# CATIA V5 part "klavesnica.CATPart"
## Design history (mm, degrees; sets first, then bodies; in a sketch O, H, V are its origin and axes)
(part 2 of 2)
  Draft30: PullDir end face of Pocket19, Angle 33, SupportToDraft (face of Pocket19 from Sketch48.A1; face of Pocket19 from Sketch48.A2; face of Pocket19 from Sketch48.A3; face of Pocket19 from Sketch48.A10; face of Pocket19 from Sketch48.A11; face of Pocket19 from Sketch48.A12; face of Pocket19 from Sketch48.A13; face of Pocket19 from Sketch48.A4; face of Pocket19 from Sketch48.L1; face of Pocket19 from Sketch48.A5; face of Pocket19 from Sketch48.L2; face of Pocket19 from Sketch48.A6; face of Pocket19 from Sketch48.L3; face of Pocket19 from Sketch48.A7; face of Pocket19 from Sketch48.L4; face of Pocket19 from Sketch48.A8; face of Pocket19 from Sketch48.L5; face of Pocket19 from Sketch48.A9; face of Pocket19 from Sketch48.L6), Neutral end face of Pocket19
  Fillet15: radius 0.5, on edge [end face of Pocket19 | face of Pocket19 from Sketch48.A1]; edge [end face of Pocket19 | face of Pocket19 from Sketch48.A2]; edge [end face of Pocket19 | face of Pocket19 from Sketch48.A3]; edge [end face of Pocket19 | face of Pocket19 from Sketch48.A10]; edge [end face of Pocket19 | face of Pocket19 from Sketch48.A11]; edge [end face of Pocket19 | face of Pocket19 from Sketch48.A12]; edge [end face of Pocket19 | face of Pocket19 from Sketch48.A13]; edge [end face of Pocket19 | face of Pocket19 from Sketch48.A4]; edge [end face of Pocket19 | face of Pocket19 from Sketch48.L1]; edge [end face of Pocket19 | face of Pocket19 from Sketch48.A5]; edge [end face of Pocket19 | face of Pocket19 from Sketch48.L2]; edge [end face of Pocket19 | face of Pocket19 from Sketch48.A6]; edge [end face of Pocket19 | face of Pocket19 from Sketch48.L3]; edge [end face of Pocket19 | face of Pocket19 from Sketch48.A7]; edge [end face of Pocket19 | face of Pocket19 from Sketch48.L4]; edge [end face of Pocket19 | face of Pocket19 from Sketch48.A8]; edge [end face of Pocket19 | face of Pocket19 from Sketch48.L5]; edge [end face of Pocket19 | face of Pocket19 from Sketch48.A9]; edge [end face of Pocket19 | face of Pocket19 from Sketch48.L6]
  Fillet16: radius 0.5, on edge [face of Pocket19 from Sketch48.A1 | start face of Pad1]; edge [face of Pocket19 from Sketch48.A2 | start face of Pad1]; edge [face of Pocket19 from Sketch48.A3 | start face of Pad1]; edge [face of Pocket19 from Sketch48.A10 | start face of Pad1]; edge [face of Pocket19 from Sketch48.A11 | start face of Pad1]; edge [face of Pocket19 from Sketch48.A12 | start face of Pad1]; edge [face of Pocket19 from Sketch48.A13 | start face of Pad1]; edge [face of Pocket19 from Sketch48.A4 | start face of Pad1]; edge [face of Pocket19 from Sketch48.L1 | start face of Pad1]; edge [face of Pocket19 from Sketch48.A5 | start face of Pad1]; edge [face of Pocket19 from Sketch48.L2 | start face of Pad1]; edge [face of Pocket19 from Sketch48.A6 | start face of Pad1]; edge [face of Pocket19 from Sketch48.L3 | start face of Pad1]; edge [face of Pocket19 from Sketch48.A7 | start face of Pad1]; edge [face of Pocket19 from Sketch48.L4 | start face of Pad1]; edge [face of Pocket19 from Sketch48.A8 | start face of Pad1]; edge [face of Pocket19 from Sketch48.L5 | start face of Pad1]; edge [face of Pocket19 from Sketch48.A9 | start face of Pad1]; edge [face of Pocket19 from Sketch48.L6 | start face of Pad1]
  Sketch49 on start face of Pad1, origin (0, 0, 0), H (1, 0, 0), V (0, -1, 0)
    line L1 (-17, -10.5) -> (-17, -7.5)
    line L2 (-10, -7.5) -> (-10, -10.5)
    arc A1 centre (-13.5, -7.5) radius 3.5 from (-17, -7.5) to (-10, -7.5) cw
    arc A2 centre (-13.5, -10.5) radius 3.5 from (-10, -10.5) to (-17, -10.5) cw
    line L3 (-6, -3.5) -> (-3, -3.5)
    line L4 (-3, 3.5) -> (-6, 3.5)
    arc A3 centre (-6, 0) radius 3.5 from (-6, 3.5) to (-6, -3.5) ccw
    arc A4 centre (-3, 0) radius 3.5 from (-3, -3.5) to (-3, 3.5) ccw
    line L5 (-10, 7.5) -> (-10, 10.5)
    line L6 (-17, 10.5) -> (-17, 7.5)
    arc A5 centre (-13.5, 10.5) radius 3.5 from (-10, 10.5) to (-17, 10.5) ccw
    arc A6 centre (-13.5, 7.5) radius 3.5 from (-17, 7.5) to (-10, 7.5) ccw
    arc A7 centre (-21, 0) radius 3.5 from (-21, 3.5) to (-21, -3.5) cw
    arc A8 centre (-24, 0) radius 3.5 from (-24, -3.5) to (-24, 3.5) cw
    line L7 (-24, 3.5) -> (-21, 3.5)
    line L8 (-21, -3.5) -> (-24, -3.5)
  Pocket20: profile Sketch49, direction (0, 0, 1), length 1, opposite side up to start face of Pad1
  Draft31: PullDir end face of Pocket20, Angle 33, SupportToDraft (face of Pocket20 from Sketch49.L1; face of Pocket20 from Sketch49.A1; face of Pocket20 from Sketch49.L2; face of Pocket20 from Sketch49.A2; face of Pocket20 from Sketch49.L3; face of Pocket20 from Sketch49.A4; face of Pocket20 from Sketch49.L4; face of Pocket20 from Sketch49.A3; face of Pocket20 from Sketch49.L5; face of Pocket20 from Sketch49.A5; face of Pocket20 from Sketch49.L6; face of Pocket20 from Sketch49.A6; face of Pocket20 from Sketch49.A7; face of Pocket20 from Sketch49.L8; face of Pocket20 from Sketch49.A8; face of Pocket20 from Sketch49.L7), Neutral end face of Pocket20
  Fillet17: radius 0.5, on edge [end face of Pocket20 | face of Pocket20 from Sketch49.L1]; edge [end face of Pocket20 | face of Pocket20 from Sketch49.A1]; edge [end face of Pocket20 | face of Pocket20 from Sketch49.L2]; edge [end face of Pocket20 | face of Pocket20 from Sketch49.A2]; edge [end face of Pocket20 | face of Pocket20 from Sketch49.L3]; edge [end face of Pocket20 | face of Pocket20 from Sketch49.A4]; edge [end face of Pocket20 | face of Pocket20 from Sketch49.L4]; edge [end face of Pocket20 | face of Pocket20 from Sketch49.A3]; edge [end face of Pocket20 | face of Pocket20 from Sketch49.L5]; edge [end face of Pocket20 | face of Pocket20 from Sketch49.A5]; edge [end face of Pocket20 | face of Pocket20 from Sketch49.L6]; edge [end face of Pocket20 | face of Pocket20 from Sketch49.A6]; edge [end face of Pocket20 | face of Pocket20 from Sketch49.A7]; edge [end face of Pocket20 | face of Pocket20 from Sketch49.L8]; edge [end face of Pocket20 | face of Pocket20 from Sketch49.A8]; edge [end face of Pocket20 | face of Pocket20 from Sketch49.L7]
  Fillet18: radius 0.5, on edge [face of Pocket20 from Sketch49.L1 | start face of Pad1]; edge [face of Pocket20 from Sketch49.A1 | start face of Pad1]; edge [face of Pocket20 from Sketch49.L2 | start face of Pad1]; edge [face of Pocket20 from Sketch49.A2 | start face of Pad1]; edge [face of Pocket20 from Sketch49.L3 | start face of Pad1]; edge [face of Pocket20 from Sketch49.A4 | start face of Pad1]; edge [face of Pocket20 from Sketch49.L4 | start face of Pad1]; edge [face of Pocket20 from Sketch49.A3 | start face of Pad1]; edge [face of Pocket20 from Sketch49.L5 | start face of Pad1]; edge [face of Pocket20 from Sketch49.A5 | start face of Pad1]; edge [face of Pocket20 from Sketch49.L6 | start face of Pad1]; edge [face of Pocket20 from Sketch49.A6 | start face of Pad1]; edge [face of Pocket20 from Sketch49.A7 | start face of Pad1]; edge [face of Pocket20 from Sketch49.L8 | start face of Pad1]; edge [face of Pocket20 from Sketch49.A8 | start face of Pad1]; edge [face of Pocket20 from Sketch49.L7 | start face of Pad1]
  Sketch50 on start face of Pad1, origin (0, 0, 0), H (1, 0, 0), V (0, -1, 0)
    circle A1 centre (20.4629, 14.0037) radius 3.5
  Pocket21: profile Sketch50, direction (0, 0, 1), length 1, opposite side up to start face of Pad1
  Draft32: PullDir end face of Pocket21, Angle 33, SupportToDraft face of Pocket21 from Sketch50.A1, Neutral end face of Pocket21
  Fillet19: radius 0.5, on edge [face of Pocket21 from Sketch50.A1 | end face of Pocket21]
  Fillet20: radius 0.5, on edge [face of Pocket21 from Sketch50.A1 | start face of Pad1]
  Sketch51 on start face of Pad1, origin (0, 0, 0), H (1, 0, 0), V (0, -1, 0)
    circle A1 centre (29.9629, 14.0037) radius 3.5
  Pocket22: profile Sketch51, direction (0, 0, 1), length 1, opposite side up to start face of Pad1
  Draft33: PullDir end face of Pocket22, Angle 33, SupportToDraft face of Pocket22 from Sketch51.A1, Neutral end face of Pocket22
  Fillet21: radius 0.5, on edge [face of Pocket22 from Sketch51.A1 | end face of Pocket22]
  Fillet22: radius 0.5, on edge [face of Pocket22 from Sketch51.A1 | start face of Pad1]
  Sketch52 on start face of Pad1, origin (0, 0, 0), H (1, 0, 0), V (0, -1, 0)
    circle A1 centre (12, 0) radius 3.5
  Pocket23: profile Sketch52, direction (0, 0, 1), length 1, opposite side up to start face of Pad1
  Draft34: PullDir end face of Pocket23, Angle 33, SupportToDraft face of Pocket23 from Sketch52.A1, Neutral end face of Pocket23
  Fillet23: radius 0.5, on edge [face of Pocket23 from Sketch52.A1 | end face of Pocket23]
  Fillet24: radius 0.5, on edge [face of Pocket23 from Sketch52.A1 | start face of Pad1]
  Sketch53 on start face of Pad1, origin (0, 0, 0), H (1, 0, 0), V (0, -1, 0)
    circle A1 centre (0.8728, -12.5) radius 4.5
    circle A2 centre (0.8728, 12.5) radius 4.5
  Pocket24: profile Sketch53, direction (0, 0, 1), length 1, opposite side up to start face of Pad1
  Draft35: PullDir end face of Pocket24, Angle 33, SupportToDraft (face of Pocket24 from Sketch53.A1; face of Pocket24 from Sketch53.A2), Neutral end face of Pocket24
  Fillet25: radius 0.5, on edge [end face of Pocket24 | face of Pocket24 from Sketch53.A1]; edge [end face of Pocket24 | face of Pocket24 from Sketch53.A2]
  Fillet26: radius 0.5, on edge [face of Pocket24 from Sketch53.A1 | start face of Pad1]; edge [face of Pocket24 from Sketch53.A2 | start face of Pad1]
  Sketch54 on start face of Pad1, origin (0, 0, 0), H (1, 0, 0), V (0, -1, 0)
    circle A1 centre (-27.8728, 12.5) radius 4.5
    circle A2 centre (-27.8728, -12.5) radius 4.5
  Pocket25: profile Sketch54, direction (0, 0, 1), length 1, opposite side up to start face of Pad1
  Draft36: PullDir end face of Pocket25, Angle 33, SupportToDraft (face of Pocket25 from Sketch54.A1; face of Pocket25 from Sketch54.A2), Neutral end face of Pocket25
  Fillet27: radius 0.5, on edge [end face of Pocket25 | face of Pocket25 from Sketch54.A1]; edge [end face of Pocket25 | face of Pocket25 from Sketch54.A2]
  Fillet28: radius 0.5, on edge [face of Pocket25 from Sketch54.A1 | start face of Pad1]; edge [face of Pocket25 from Sketch54.A2 | start face of Pad1]
  Sketch55 on start face of Pad1, origin (0, 0, 0), H (1, 0, 0), V (0, -1, 0)
    arc A1 centre (9.6384, -13.9416) radius 5 from (13.2757, -17.3723) to (14.3786, -12.351) ccw
    point P3 (11.8207, -18)
    arc A2 centre (11.8207, -16) radius 2 from (13.2757, -17.3723) to (11.8207, -18) cw
    point P4 (11.8207, -18)
    arc A3 centre (11.8207, -16) radius 2 from (10.3658, -17.3723) to (11.8207, -18) ccw
    arc A4 centre (14.0031, -13.9416) radius 5 from (10.3658, -17.3723) to (9.2628, -12.351) cw
    arc A5 centre (13.9293, -14.134) radius 5 from (9.3483, -12.1304) to (10.415, -10.5773) cw
    point P9 (11.8207, -10)
    arc A6 centre (11.8207, -12) radius 2 from (11.8207, -10) to (10.415, -10.5773) ccw
    line L1 (9.2628, -12.351) -> (9.3483, -12.1304)
    point P11 (11.8207, -10)
    arc A7 centre (11.8207, -12) radius 2 from (11.8207, -10) to (13.2265, -10.5773) cw
    arc A8 centre (9.7122, -14.134) radius 5 from (14.2932, -12.1304) to (13.2265, -10.5773) ccw
    line L2 (14.3786, -12.351) -> (14.2932, -12.1304)
    coincidence: P3 P4, P9 P11
  Pocket26: profile Sketch55, direction (0, 0, 1), length 1
  Sketch56 on start face of Pad1, origin (0, 0, 0), H (1, 0, 0), V (0, -1, 0)
    arc A1 centre (56.6247, 13) radius 4 from (60.5344, 13.8452) to (60.5344, 12.1548) ccw
    arc A2 centre (60, 13) radius 1 from (60.5344, 12.1548) to (60.5344, 13.8452) ccw
    reference projected line E1 (-64, 20) -> (64, 20) from edge [start face of Pad1 | face of Pocket9]
    distance E1 A1 = 3
  Pocket27: profile Sketch56, direction (0, 0, 1), length 1
  Fillet29: radius 1, on end face of Pocket27, deactivated
  Sketch57 on start face of Pad1, origin (0, 0, 0), H (1, 0, 0), V (0, -1, 0)
    arc A1 centre (9.6384, 13.9416) radius 5 from (13.2757, 17.3723) to (14.3786, 12.351) cw
    arc A2 centre (9.7122, 14.134) radius 5 from (14.2932, 12.1304) to (13.2265, 10.5773) cw
    line L1 (14.3786, 12.351) -> (14.2932, 12.1304)
    point P5 (11.8207, 10)
    arc A3 centre (11.8207, 12) radius 2 from (11.8207, 10) to (13.2265, 10.5773) ccw
    point P7 (11.8207, 10)
    arc A4 centre (11.8207, 12) radius 2 from (11.8207, 10) to (10.415, 10.5773) cw
    arc A5 centre (13.9293, 14.134) radius 5 from (9.3483, 12.1304) to (10.415, 10.5773) ccw
    line L2 (9.2628, 12.351) -> (9.3483, 12.1304)
    arc A6 centre (14.0031, 13.9416) radius 5 from (10.3658, 17.3723) to (9.2628, 12.351) ccw
    point P11 (11.8207, 18)
    arc A7 centre (11.8207, 16) radius 2 from (10.3658, 17.3723) to (11.8207, 18) cw
    point P12 (11.8207, 18)
    arc A8 centre (11.8207, 16) radius 2 from (13.2757, 17.3723) to (11.8207, 18) ccw
    coincidence: P5 P7, P11 P12
  Pocket28: profile Sketch57, direction (0, 0, 1), length 1
  Fillet30: radius 0.9, on end face of Pocket28
  Fillet31: radius 0.9, on end face of Pocket27
  Fillet32: radius 0.9, on end face of Pocket26
  Sketch58 on end face of Pocket19, origin (0, 0, 1), H (1, 0, 0), V (0, -1, 0)
    circle A1 centre (47.4629, 9.2505) radius 0.75
  Pad28: profile Sketch58, direction (0, 0, 1), length 0.5
  Plane1: type Offset, RefPlane face of Pad28, Offset 0, reversed
  Sketch59 on Plane1, origin (0, 0, 1), H (1, 0, 0), V (0, 1, 0)
    circle A1 centre (47.4631, -9.3215) radius 0.75
    point P1 (47.4631, -9.3215)
    reference projected line E1 (44.0421, -10.5) -> (44.0421, -15.5) from edge [face of Fillet16 | start face of Pad1]
    reference projected arc E2 centre (47.463, -10.5) radius 2.2285 from (49.6915, -10.5) to (45.2345, -10.5) ccw from edge [face of Fillet15 | end face of Pocket19]
    circle A2 centre (47.4631, -16.6785) radius 0.75
    point P2 (47.4631, -16.6785)
    reference projected line E3 (44.0421, -10.5) -> (44.0421, -15.5) from edge [face of Fillet16 | start face of Pad1]
    reference projected arc E4 centre (47.463, -15.5) radius 2.2285 from (45.2345, -15.5) to (49.6915, -15.5) ccw from edge [face of Fillet15 | end face of Pocket19]
    circle A3 centre (47.4631, 16.6785) radius 0.75
    circle A4 centre (47.4631, 9.3215) radius 0.75
    radius A1 = 0.75
    distance E1 P1 = 3.421
    distance A1 E2 = 0.3
    radius A2 = 0.75
    distance E3 P2 = 3.421
    distance A2 E4 = 0.3
    symmetry: A2 A3 H, A1 A4 H
  Pad29: profile Sketch59, direction (0, 0, -1), length 0.5
  Sketch60 on Plane1, origin (0, 0, 1), H (1, 0, 0), V (0, 1, 0)
    circle A1 centre (47.4631, 3.6785) radius 0.75
    point P1 (47.4631, 3.6785)
    circle A2 centre (47.4631, -3.6785) radius 0.75
    point P2 (47.4631, -3.6785)
    reference projected line E1 (44.0421, 2.5) -> (44.0421, -2.5) from edge [face of Fillet16 | start face of Pad1]
    reference projected line E2 (44.0421, 2.5) -> (44.0421, -2.5) from edge [face of Fillet16 | start face of Pad1]
    reference projected arc E3 centre (47.463, 2.5) radius 2.2285 from (49.6915, 2.5) to (45.2345, 2.5) ccw from edge [face of Fillet15 | end face of Pocket19]
    reference projected arc E4 centre (47.463, -2.5) radius 2.2285 from (45.2345, -2.5) to (49.6915, -2.5) ccw from edge [face of Fillet15 | end face of Pocket19]
    radius A2 = 0.75
    radius A1 = 0.75
    distance P1 E1 = 3.421
    distance P2 E2 = 3.421
    distance A1 E3 = 0.3
    distance A2 E4 = 0.3
  Pad30: profile Sketch60, direction (0, 0, -1), length 0.5
  Sketch61 on Plane1, origin (0, 0, 1), H (1, 0, 0), V (0, 1, 0)
    circle A1 centre (11.8, -11.6796) radius 0.75
    circle A2 centre (11.8, -16.1) radius 0.75
    circle A3 centre (11.8, 16.1) radius 0.75
    circle A4 centre (11.8, 11.6796) radius 0.75
    symmetry: A2 A3 H, A1 A4 H
  Pad31: profile Sketch61, direction (0, 0, -1), length 0.5
  Sketch62 on face of Pocket6, origin (0, 0, 1), H (1, 0, 0), V (0, 1, 0)
    reference projected line E1 (-64, 20) -> (-64, 19) from edge [face of Pad3 | face of Pad4]
    reference projected line E4 (64, -17) -> (64, -12) from edge [face of Pocket9 | face of Pad5]
    distance E1 E4 = 128 (reference)
  Sketch63 on xy-plane, origin (0, 0, 0), H (1, 0, 0), V (0, 1, 0)
    line L1 (-64, -20) -> (64, -20)
    point P2 (64, -20)
    line L2 (-64, -20) -> (-64, 20)
    point P3 (-64, 20)
    line L3 (64, -20) -> (64, -7)
    line L4 (-64, 20) -> (52, 20)
    line L5 (52, 20) -> (52, -7)
    line L6 (64, -7) -> (52, -7)
    circle A1 centre (12, 0) radius 3.5
    circle A2 centre (20.4629, 14.0037) radius 3.5
    circle A3 centre (29.9629, 14.0037) radius 3.5
    length L1 = 128
    distance P2 V = 64
    length L2 = 40
    distance P3 H = 20
    length L3 = 13
    length L4 = 116
    horizontal: L1 H, L4 H, L6 H
    vertical: L2 V, L3 V, L5 V
  Pad32: profile Sketch63, direction (0, 0, 1), length 1, deactivated
  Sketch64 on xy-plane, origin (0, 0, 0), H (1, 0, 0), V (0, 1, 0)
    line L1 (-64, -20) -> (64, -20)
    point P2 (64, -20)
    line L2 (-64, -20) -> (-64, 20)
    point P3 (-64, 20)
    line L3 (64, -20) -> (64, -7)
    line L4 (-64, 20) -> (52, 20)
    line L5 (52, 20) -> (52, -7)
    line L6 (64, -7) -> (52, -7)
    circle A1 centre (-49, -4.6) radius 3
    circle A2 centre (-49, 4.6) radius 3
    circle A3 centre (-49, 13.8) radius 3
    circle A4 centre (-58, 13.8) radius 3
    circle A5 centre (-58, 4.6) radius 3
    circle A6 centre (-58, -4.6) radius 3
    circle A7 centre (-49, -13.8) radius 3
    length L1 = 128
    distance P2 V = 64
    length L2 = 40
    distance P3 H = 20
    length L3 = 13
    length L4 = 116
    horizontal: L1 H, L4 H, L6 H
    vertical: L2 V, L3 V, L5 V
  Pad33: profile Sketch64, direction (0, 0, 1), length 1, deactivated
